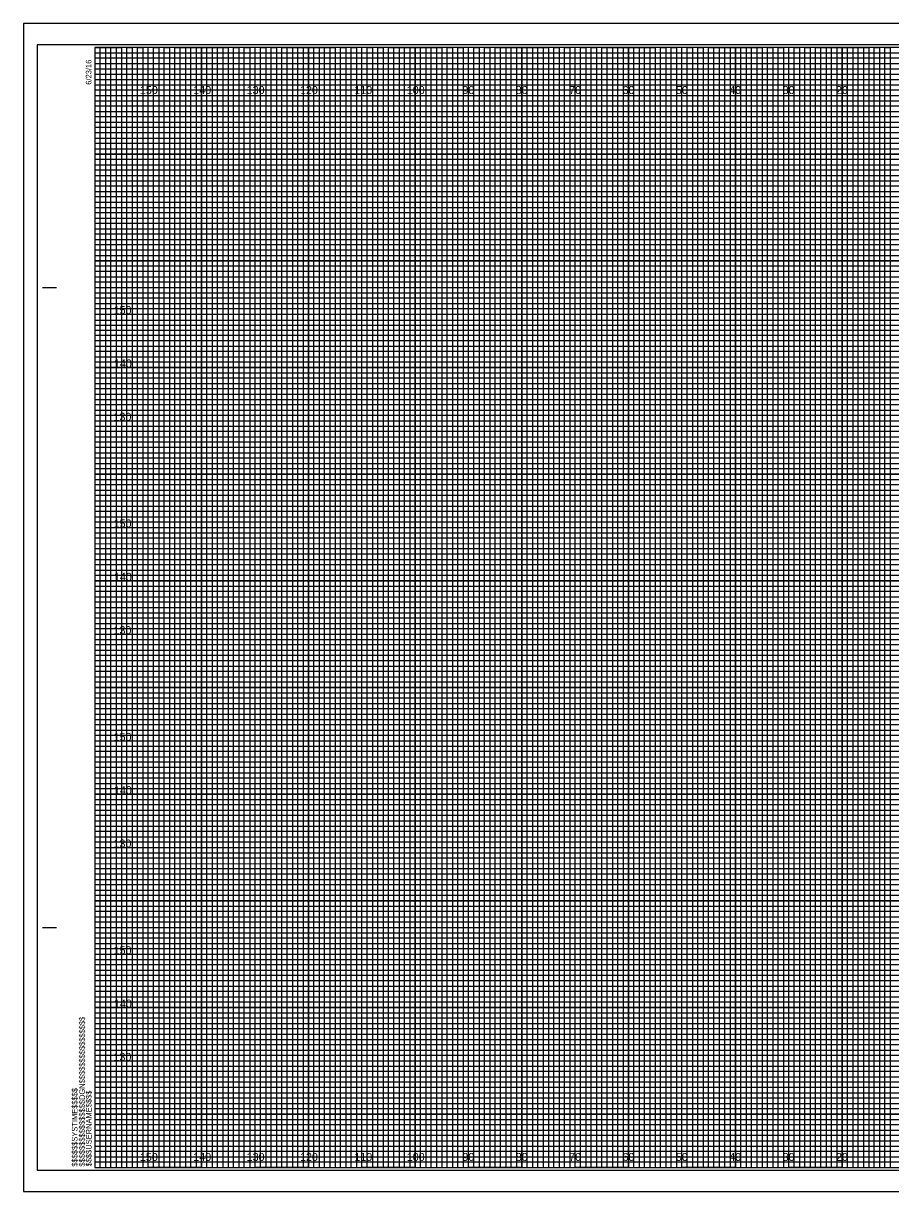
# Model space of a CAD drawing. Extents: x -13 to 323, y -5 to 1094.
# Drawn here: x -13.4 to 149.1, y 215.5 to 434.5 of the extents above; entities that cross this region are included whole.
import ezdxf

# ---------------------------------------------------------------- set-up
doc = ezdxf.new("R2010")
doc.units = 0
for name, color, linetype in [('Exist Cross Section Cell', 7, 'Continuous'), ('Exist XS Center Line Elevation Label', 7, 'Continuous'), ('Exist XS Ground Line', 7, 'Continuous'), ('Prop CMT Pvmt Course 1', 7, 'Continuous'), ('Prop CMT Pvmt Course 3', 7, 'Continuous'), ('Prop CMT Pvmt Surface', 7, 'Continuous'), ('Prop CMT Pvmt Surface Shoulder', 7, 'Continuous'), ('Prop CMT Shld Paved Course 1', 7, 'Continuous'), ('Prop CMT Shld Paved Course 2', 7, 'Continuous'), ('Prop CMT Shld Paved Course 3', 7, 'Continuous'), ('Prop CMT Subgrade Earthwork', 7, 'Continuous')]:
    doc.layers.add(name, color=color, linetype=linetype)

msp = doc.modelspace()

# ---------------------------------------------------------------- linework, layer by layer
at = {"layer": 'Exist XS Center Line Elevation Label'}
for points in [[(0, 430), (5, 430), (5, 220), (15, 220), (15, 430), (25, 430), (25, 220), (35, 220), (35, 430), (45, 430), (45, 220), (55, 220), (55, 430), (65, 430), (65, 220), (75, 220), (75, 430), (85, 430), (85, 220), (95, 220), (95, 430), (105, 430), (105, 220), (115, 220), (115, 430), (125, 430), (125, 220), (135, 220), (135, 430), (145, 430), (145, 220), (155, 220)], [(0, 425), (275, 425)], [(0, 405), (320, 405), (320, 415), (0, 415)], [(0, 385), (320, 385), (320, 395), (0, 395)], [(0, 365), (320, 365), (320, 375), (0, 375)], [(0, 345), (320, 345), (320, 355), (0, 355)], [(0, 325), (320, 325), (320, 335), (0, 335)], [(0, 305), (320, 305), (320, 315), (0, 315)], [(0, 285), (320, 285), (320, 295), (0, 295)], [(0, 265), (320, 265), (320, 275), (0, 275)], [(0, 245), (320, 245), (320, 255), (0, 255)], [(0, 225), (320, 225), (320, 235), (0, 235)]]:
    msp.add_lwpolyline(points, dxfattribs=at)
at = {"layer": 'Exist XS Ground Line'}
for p, q in [((10, 430), (0, 430)), ((10, 220), (10, 430)), ((30, 430), (20, 430)), ((20, 430), (20, 220)), ((30, 220), (30, 430)), ((50, 430), (40, 430)), ((40, 430), (40, 220)), ((50, 220), (50, 430)), ((70, 430), (60, 430)), ((60, 430), (60, 220)), ((70, 220), (70, 430)), ((90, 430), (80, 430)), ((80, 430), (80, 220)), ((90, 220), (90, 430)), ((110, 430), (100, 430)), ((100, 430), (100, 220)), ((110, 220), (110, 430)), ((130, 430), (120, 430)), ((120, 430), (120, 220)), ((130, 220), (130, 430)), ((150, 430), (140, 430)), ((140, 430), (140, 220)), ((20, 220), (10, 220)), ((40, 220), (30, 220)), ((60, 220), (50, 220)), ((80, 220), (70, 220)), ((100, 220), (90, 220)), ((120, 220), (110, 220)), ((140, 220), (130, 220))]:
    msp.add_line(p, q, dxfattribs=at)
for points in [[(0, 420), (320, 420), (320, 410), (0, 410)], [(0, 400), (320, 400), (320, 390), (0, 390)], [(0, 380), (320, 380), (320, 370), (0, 370)], [(0, 360), (320, 360), (320, 350), (0, 350)], [(0, 340), (320, 340), (320, 330), (0, 330)], [(0, 320), (320, 320), (320, 310), (0, 310)], [(0, 300), (320, 300), (320, 290), (0, 290)], [(0, 280), (320, 280), (320, 270), (0, 270)], [(0, 260), (320, 260), (320, 250), (0, 250)], [(0, 240), (320, 240), (320, 230), (0, 230)]]:
    msp.add_lwpolyline(points, dxfattribs=at)
at = {"layer": 'Prop CMT Pvmt Course 3'}
msp.add_lwpolyline([(-13.4, 215.5), (323.3, 215.5), (323.3, 434.5), (-13.4, 434.5)], close=True, dxfattribs=at)
at = {"layer": 'Prop CMT Pvmt Surface'}
for p, q in [((10, 220), (10, 430)), ((20, 220), (20, 430)), ((30, 220), (30, 430)), ((40, 220), (40, 430)), ((50, 220), (50, 430)), ((60, 220), (60, 430)), ((70, 220), (70, 430)), ((80, 220), (80, 430)), ((90, 220), (90, 430)), ((100, 220), (100, 430)), ((110, 220), (110, 430)), ((120, 220), (120, 430)), ((130, 220), (130, 430)), ((140, 220), (140, 430)), ((0, 420), (320, 420)), ((0, 410), (320, 410)), ((0, 400), (320, 400)), ((0, 390), (320, 390)), ((0, 380), (320, 380)), ((0, 370), (320, 370)), ((0, 360), (320, 360)), ((0, 350), (320, 350)), ((0, 340), (320, 340)), ((0, 330), (320, 330)), ((0, 320), (320, 320)), ((0, 310), (320, 310)), ((0, 300), (320, 300)), ((0, 290), (320, 290)), ((0, 280), (320, 280)), ((0, 270), (320, 270)), ((0, 260), (320, 260)), ((0, 250), (320, 250)), ((0, 240), (320, 240)), ((0, 230), (320, 230))]:
    msp.add_line(p, q, dxfattribs=at)
at = {"layer": 'Prop CMT Pvmt Surface Shoulder'}
for p, q in [((323.3, 434.5), (-13.4, 434.5)), ((-13.4, 434.5), (-13.4, 215.5)), ((-13.4, 215.5), (323.3, 215.5))]:
    msp.add_line(p, q, dxfattribs=at)
at = {"layer": 'Prop CMT Shld Paved Course 1'}
for p, q in [((0, 429), (260, 429)), ((260, 427.98), (0, 427.98)), ((0, 427.98), (0, 427)), ((0, 427), (260, 427)), ((260, 425.89), (0, 425.89)), ((0, 425.89), (0, 424)), ((0, 424), (320, 424))]:
    msp.add_line(p, q, dxfattribs=at)
for points in [[(0, 423), (270, 423), (320, 423), (320, 422), (0, 422)], [(0, 421), (320, 421), (320, 419), (0, 419)], [(0, 418), (320, 418), (320, 417), (0, 416.98)], [(0, 416), (320, 416), (320, 414), (0, 414)], [(0, 413), (320, 413), (320, 412), (0, 412)], [(0, 411), (320, 411), (320, 409), (0, 409)], [(0, 408), (320, 408), (320, 407), (0, 407)], [(0, 406), (320, 406), (320, 404), (0, 404)], [(0, 403), (320, 403), (320, 402), (0, 402)], [(0, 401), (320, 401), (320, 399), (0, 399)], [(0, 398), (320, 398), (320, 397), (0, 397)], [(0, 396), (320, 396), (320, 393.95), (320, 393), (320, 392), (0, 392)], [(0, 394), (320, 394), (320, 393), (0, 393)], [(0, 391), (320, 391), (320, 389), (0, 389.03)], [(0, 389.03), (320, 389), (320, 388), (0, 388)], [(0, 387), (320, 387), (320, 386), (0, 386)], [(0, 384), (320, 384), (320, 383), (0, 383)], [(0, 382), (320, 382), (320, 381), (0, 381)], [(-0.07, 378.89), (320, 378.89), (320, 377.88), (-0.07, 377.88)], [(0, 377), (320, 377), (320, 376), (0, 376)], [(0, 374), (320, 374), (320, 373), (0, 373)], [(0, 372), (320, 372), (320, 371), (0, 371)], [(0, 369), (320, 369), (320, 368), (0, 368)], [(0, 367), (320, 367), (320, 366), (0, 366)], [(0, 364), (320, 364), (320, 363), (0, 363)], [(0, 362), (320, 362), (320, 361), (0, 361)], [(0, 359), (320, 359), (319.99, 357.98), (0, 358)], [(0, 357), (320, 357), (320, 356), (0, 356)], [(0, 354), (320, 354), (320, 353), (0, 353)], [(0, 352), (320, 352), (320, 351), (0, 351)], [(0, 349), (320, 349), (320, 348), (0, 348)], [(0, 347), (320, 347), (320, 346), (0, 346)], [(0, 344), (320, 344), (320, 343), (0, 343)], [(0, 342), (320, 342), (320, 341), (0, 341)], [(0, 339), (320, 339), (320, 338), (0, 338)], [(0, 336.99), (320.07, 336.91), (320, 336), (0, 336)], [(0, 334), (320, 334), (320, 333), (0, 333)], [(0, 332), (320, 332), (320, 331), (0, 331)], [(0, 329), (320, 329), (320, 328), (0, 328)], [(0, 327), (320, 327), (320, 326), (0, 326)], [(0, 324), (320, 324), (320, 323), (0, 323)], [(0, 322), (320, 322), (320, 321), (0, 321)], [(0, 319), (320, 319), (320, 318), (0, 318)], [(0, 317), (320, 317), (320, 316), (0, 316)], [(0, 314), (320, 314), (320, 313), (0, 313)], [(0, 312), (320, 312), (320, 311), (0, 311)], [(0, 309), (320, 309), (320, 308), (0, 308)], [(0, 307), (320, 307), (320, 306), (0, 306)], [(0, 304), (320, 304), (320, 303), (0, 303)], [(0, 302), (320, 302), (320, 301), (0, 301)], [(0, 299), (320, 299), (319.99, 297.98), (0, 298)], [(0, 297), (320, 297), (320, 296), (0, 296)], [(0, 294), (320, 294), (320, 293), (0, 293)], [(0, 292), (320, 292), (320, 291), (0, 291)], [(0, 289), (320, 289), (320, 288), (0, 288)], [(0, 287), (320, 287), (320, 286), (0, 286)], [(0, 284), (320, 284), (320, 283), (0, 283)], [(0, 282), (320, 282), (320, 281), (0, 281)], [(0, 279), (320, 279), (320, 278), (0, 278)], [(0, 276.99), (320.07, 276.91), (320, 276), (0, 276)], [(0, 274), (320, 274), (320, 273), (0, 273)], [(0, 272), (320, 272), (320, 271), (0, 271)], [(0, 269), (320, 269), (320, 268), (0, 268)], [(0, 267), (320, 267), (320, 266), (0, 266)], [(0, 264), (320, 264), (320, 263), (0, 263)], [(0, 262), (320, 262), (320, 261), (0, 261)], [(0, 259), (320, 259), (320, 258), (0, 258)], [(0, 257), (320, 257), (320, 256), (0, 256)], [(0, 254), (320, 254), (320, 253), (0, 253)], [(0, 252), (320, 252), (320, 251), (0, 251)], [(0, 249), (320, 249), (320, 248), (0, 248)], [(0, 247), (320, 247), (320, 246), (0, 246)], [(0, 244), (320, 244), (320, 243), (0, 243)], [(0, 242), (320, 242), (320, 241), (0, 241)], [(0, 239), (320, 239), (320, 238), (0, 238)], [(0, 237), (320, 237), (320, 236), (0, 236)], [(0, 234), (320, 234), (320, 233), (0, 233)], [(0, 232), (320, 232), (320, 231), (0, 231)], [(0, 229), (320, 229), (320, 228), (0, 228)], [(0, 227), (320, 227), (320, 226), (0, 226)], [(0, 224), (320, 224), (320, 223), (0, 223)], [(0, 222), (320, 222), (320, 221), (0, 221)]]:
    msp.add_lwpolyline(points, dxfattribs=at)
at = {"layer": 'Prop CMT Shld Paved Course 2'}
for p, q in [((-9.8, 385), (-7.3, 385)), ((-9.7, 385), (-7.2, 385)), ((-9.8, 265), (-7.3, 265)), ((-9.7, 265), (-7.2, 265)), ((0, 220), (0, 220)), ((0, 220), (0, 220)), ((0, 220), (0, 220)), ((0, 220), (0, 220)), ((0, 220), (0, 220)), ((0, 220), (0, 220)), ((0, 220), (0, 220))]:
    msp.add_line(p, q, dxfattribs=at)
msp.add_lwpolyline([(320, 430), (0, 430), (0, 220), (320, 220)], close=True, dxfattribs=at)
at = {"layer": 'Prop CMT Shld Paved Course 3'}
for points in [[(0, 220), (1, 220), (1, 430), (2, 430), (2, 220)], [(2, 220), (3, 220), (3, 430), (4, 430), (4, 220)], [(5, 220), (6, 220), (6, 430), (7, 430), (7, 220)], [(7, 220), (8, 220), (8, 430), (9, 430), (9, 220)], [(10, 220), (11, 220), (11, 430), (12, 430), (12, 220)], [(12, 220), (13, 220), (13, 430), (14, 430), (14, 220)], [(15, 220), (16, 220), (16, 430), (17, 430), (17, 220)], [(17, 220), (18, 220), (18, 430), (19, 430), (19, 220)], [(20, 220), (21, 220), (21, 430), (22, 430), (22, 220)], [(22, 220), (23, 220), (23, 430), (24, 430), (24, 220)], [(25, 220), (26, 220), (26, 430), (27, 430), (27, 220)], [(27, 220), (28, 220), (28, 430), (29, 430), (29, 220)], [(30, 220), (31, 220), (31, 430), (32, 430), (32, 220)], [(32, 220), (33, 220), (33, 430), (34, 430), (34, 220)], [(35, 220), (36, 220), (36, 430), (37, 430), (37, 220)], [(37, 220), (38, 220), (38, 430), (39, 430), (39, 220)], [(40, 220), (41, 220), (41, 430), (42, 430), (42, 220)], [(42, 220), (43, 220), (43, 430), (44, 430), (44, 220)], [(45, 220), (46, 220), (46, 430), (47, 430), (47, 220)], [(47, 220), (48, 220), (48, 430), (49, 430), (49, 220)], [(50, 220), (51, 220), (51, 430), (52, 430), (52, 220)], [(52, 220), (53, 220), (53, 430), (54, 430), (54, 220)], [(55, 220), (56, 220), (56, 430), (57, 430), (57, 220)], [(57, 220), (58, 220), (58, 430), (59, 430), (59, 220)], [(60, 220), (61, 220), (61, 430), (62, 430), (62, 220)], [(62, 220), (63, 220), (63, 430), (64, 430), (64, 220)], [(65, 220), (66, 220), (66, 430), (67, 430), (67, 220)], [(67, 220), (68, 220), (68, 430), (69, 430), (69, 220)], [(70, 220), (71, 220), (71, 430), (72, 430), (72, 220)], [(72, 220), (73, 220), (73, 430), (74, 430), (74, 220)], [(75, 220), (76, 220), (76, 430), (77, 430), (77, 220)], [(77, 220), (78, 220), (78, 430), (79, 430), (79, 220)], [(80, 220), (81, 220), (81, 430), (82, 430), (82, 220)], [(82, 220), (83, 220), (83, 430), (84, 430), (84, 220)], [(85, 220), (86, 220), (86, 430), (87, 430), (87, 220)], [(87, 220), (88, 220), (88, 430), (89, 430), (89, 220)], [(90, 220), (91, 220), (91, 430), (92, 430), (92, 220)], [(92, 220), (93, 220), (93, 430), (94, 430), (94, 220)], [(95, 220), (96, 220), (96, 430), (97, 430), (97, 220)], [(97, 220), (98, 220), (98, 430), (99, 430), (99, 220)], [(100, 220), (101, 220), (101, 430), (102, 430), (102, 220)], [(102, 220), (103, 220), (103, 430), (104, 430), (104, 220)], [(105, 220), (106, 220), (106, 430), (107, 430), (107, 220)], [(107, 220), (108, 220), (108, 430), (109, 430), (109, 220)], [(110, 220), (111, 220), (111, 430), (112, 430), (112, 220)], [(112, 220), (113, 220), (113, 430), (114, 430), (114, 220)], [(115, 220), (116, 220), (116, 430), (117, 430), (117, 220)], [(117, 220), (118, 220), (118, 430), (119, 430), (119, 220)], [(120, 220), (121, 220), (121, 430), (122, 430), (122, 220)], [(122, 220), (123, 220), (123, 430), (124, 430), (124, 220)], [(125, 220), (126, 220), (126, 430), (127, 430), (127, 220)], [(127, 220), (128, 220), (128, 430), (129, 430), (129, 220)], [(130, 220), (131, 220), (131, 430), (132, 430), (132, 220)], [(132, 220), (133, 220), (133, 430), (134, 430), (134, 220)], [(135, 220), (136, 220), (136, 430), (137, 430), (137, 220)], [(137, 220), (138, 220), (138, 430), (139, 430), (139, 220)], [(140, 220), (141, 220), (141, 430), (142, 430), (142, 220)], [(142, 220), (143, 220), (143, 430), (144, 430), (144, 220)], [(145, 220), (146, 220), (146, 430), (147, 430), (147, 220)], [(147, 220), (148, 220), (148, 430), (149, 430), (149, 220)]]:
    msp.add_lwpolyline(points, dxfattribs=at)
at = {"layer": 'Prop CMT Subgrade Earthwork'}
msp.add_lwpolyline([(-10.8, 219.5), (322.4, 219.5), (322.4, 430.5), (-10.8, 430.5)], close=True, dxfattribs=at)

# ---------------------------------------------------------------- texts
at = {"layer": 'Exist Cross Section Cell'}
for s, p in [('150', (8.44, 421.25)), ('140', (18.44, 421.25)), ('130', (28.44, 421.25)), ('120', (38.44, 421.25)), ('110', (48.62, 421.25)), ('100', (58.44, 421.25)), ('90', (68.86, 421.25)), ('80', (78.86, 421.25)), ('70', (88.86, 421.25)), ('60', (98.86, 421.25)), ('50', (108.86, 421.25)), ('40', (118.86, 421.25)), ('30', (128.86, 421.25)), ('20', (138.86, 421.25)), ('150', (8.44, 221.25)), ('140', (18.44, 221.25)), ('130', (28.44, 221.25)), ('120', (38.44, 221.25)), ('110', (48.62, 221.25)), ('100', (58.44, 221.25)), ('90', (68.86, 221.25)), ('80', (78.86, 221.25)), ('70', (88.86, 221.25)), ('60', (98.86, 221.25)), ('50', (108.86, 221.25)), ('40', (118.86, 221.25)), ('30', (128.86, 221.25)), ('20', (138.86, 221.25))]:
    msp.add_text(s, height=1.5, dxfattribs=at).set_placement(p)
at = {"layer": 'Prop CMT Pvmt Course 1'}
for s, p in [('150', (3.52, 380)), ('140', (3.57, 370)), ('130', (3.49, 360)), ('150', (3.52, 340)), ('140', (3.57, 330)), ('130', (3.49, 320)), ('150', (3.52, 300)), ('140', (3.57, 290)), ('130', (3.49, 280)), ('150', (3.52, 260)), ('140', (3.57, 250)), ('130', (3.49, 240))]:
    msp.add_text(s, height=1.5, dxfattribs=at).set_placement(p)
at = {"layer": 'Prop CMT Shld Paved Course 2'}
for s, p in [('6/23/16', (-0.65, 423)), ('$$$$$$$$$$$$$$$$DGN$$$$$$$$$$$$$$$$', (-1.88, 220.18)), ('$$$$$$SYSTIME$$$$$', (-3.26, 220.18)), ('$$$$USERNAME$$$$', (-0.62, 220.23))]:
    msp.add_text(s, height=1.05, rotation=90, dxfattribs=at).set_placement(p)

doc.saveas('drawing.dxf')
